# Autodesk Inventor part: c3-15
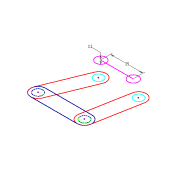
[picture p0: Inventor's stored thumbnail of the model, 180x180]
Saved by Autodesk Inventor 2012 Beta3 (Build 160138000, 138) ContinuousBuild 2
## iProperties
Created: 2011-02
Part Number: c3-15
Material: Default
Document SubType Name: Modeling
Designer: Beta-8540w
Density: 1 g/cm^3
Author: Beta-8540w
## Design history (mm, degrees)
node "Blocks"
  sketch "Link 1"
    geometry: L1 (0, -8)-(50, -8); L2 (50, 8)-(0, 8); C1 r 5 at (0, 0); C2 r 5 at (50, 0); A1 r 8 centre (50, 0) between (50, -8) and (50, 8); A2 r 8 centre (0, 0) between (0, 8) and (0, -8); 1 further point
    constraints: 4 centre point, 4 end point, 4 point on circle, 4 tangent, 3 coincident, 1 equal radius, 1 horizontal, 1 parallel
    dimensions: "d0" = 50 distance of L1.start L1.end; "d1" = 10 diameter of C1; "d2" = 8 radius of A2
sketch "Linkage"
  geometry: L1 (3.667, 63.852)-(38.667, 63.852); C1 r 5.5 at (3.667, 63.852); C2 r 5.5 at (38.667, 63.852); 1 further point
  constraints: 2 centre point, 2 end point, 1 equal radius, 1 other
  dimensions: "d3" = 11 diameter of C1; "d5" = 35 distance of L1.start L1.end
  node "Link 1:1"
  node "Link 1:2"
  node "Link 1:3"
